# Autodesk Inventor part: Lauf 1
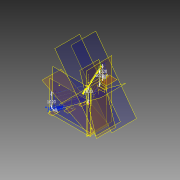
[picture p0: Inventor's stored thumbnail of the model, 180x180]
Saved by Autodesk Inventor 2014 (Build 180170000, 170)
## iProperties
Created: 2013-09
Part Number: Lauf 1
Material: Edelstahl
Document SubType Name: Modeling
Designer: Stefan Tammegger
Mass: 722.325 g
Surface Area: 345.591 cm^2
Volume: 89.3967 cm^3
Density: 8.08 g/cm^3
Appearance: Halbpoliert
Author: Stefan Tammegger
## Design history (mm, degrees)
workplane "Arbeitsebene1"
sketch "Skizze1"
  geometry: L1 (-327.111, -31.202)-(2120.889, -31.202) reference; L2 (0, 0)-(0, -500) reference; L3 (-280, 0)-(-280, -500) reference; L4 (-250, -51.202)-(-140, -51.202); L5 (-140, -51.202)-(-140, -131.202); L6 (-140, -131.202)-(-250, -131.202); L7 (-250, -131.202)-(-250, -51.202); C1 r 5.5 at (-235, -91.202); C2 r 5.5 at (-155, -91.202)
  constraints: 8 end point, 2 centre point, 2 parallel, 1 horizontal, 1 perpendicular
  dimensions: "d0" = 80 distance of L4.end L5.end; "d2" = 20 distance between parallel lines of L1 L4; "d3" = 30 distance between parallel lines of L3 L7; "d4" = 110 distance of L5.end L6.end; "d5" = 11 diameter of C1; "d6" = 15 distance from line of L7 C1.centre; "d7" = 40 distance from line of L4 C1.centre; "d8" = 11 diameter of C2; "d9" = 15 distance from line of L5 C2.centre; "d10" = 40 distance from line of L4 C2.centre
extrude "Extrusion1" new body sketch "Skizze1" distance "d11" = 6; taper "d12" = 0 deg
fillet "Rundung1" dims "d13" = 3
workplane "Arbeitsebene2"
sketch "Skizze2"
  geometry: L1 (-2417.111, -31.202)-(30.889, -31.202) reference; L2 (30.889, -31.202)-(-4.785, 1331.151) reference; L3 (268.82, -224.082)-(-1.666, 65.979) reference; L4 (0, 0)-(0, -500) reference; L5 (20.889, -51.202)-(100.889, -51.202); L6 (100.889, -51.202)-(100.889, -131.202); L7 (100.889, -131.202)-(20.889, -131.202); L8 (20.889, -131.202)-(20.889, -51.202); L9 (-2233, -51.202)-(-2337, -51.202) reference; C1 r 5.5 at (35.889, -91.202); 1 further point
  constraints: 8 end point, 2 parallel, 1 centre point, 1 horizontal, 1 perpendicular
  dimensions: "d14" = 80 distance of L5.end L6.end; "d15" = 80 distance of L5.start L5.end; "d16" = 0 distance between parallel lines of L5 L9; "d17" = 70 horizontal distance of L5.end L1.end; "d21" = 11 diameter of C1; "d22" = 15 distance from line of L8 C1.centre
extrude "Extrusion3" new body sketch "Skizze2" distance "d23" = 6; taper "d24" = 0 deg
fillet "Rundung3" dims "d25" = 3
workplane "Arbeitsebene3"
workplane "Arbeitsebene4"
sketch "Skizze4"
  geometry: L1 (-280, 0)-(-280, -500) reference; L2 (0, 0)-(0, -500) reference; L3 (-195, -51.202)-(-85, -51.202); L4 (-85, -51.202)-(-85, -131.202); L5 (-85, -131.202)-(-195, -131.202); L6 (-195, -131.202)-(-195, -51.202); L7 (-1263, -51.202)-(-1367, -51.202) reference; C1 r 5.5 at (-180, -91.202); C2 r 5.5 at (-100, -91.202); 1 further point
  constraints: 8 end point, 2 centre point, 2 parallel, 1 horizontal, 1 perpendicular
  dimensions: "d39" = 110 distance of L4.end L5.end; "d40" = 80 distance of L3.end L4.end; "d41" = 0 distance between parallel lines of L7 L3; "d42" = 85 distance between parallel lines of L1 L6; "d43" = 11 diameter of C1; "d44" = 11 diameter of C2; "d45" = 15 distance from line of L6 C1.centre; "d46" = 15 distance from line of L4 C2.centre; "d47" = 40 distance from line of L5 C1.centre; "d48" = 40 distance from line of L5 C2.centre
extrude "Extrusion5" new body sketch "Skizze4" distance "d49" = 6; taper "d50" = 0 deg
fillet "Rundung5" dims "d51" = 3
sketch "Skizze5"
  geometry: L1 (-247, -131.202)-(-143, -131.202) reference; L2 (-250, -54.202)-(-250, -128.202) reference; L3 (-210, -66.202)-(-180, -66.202); L4 (-180, -66.202)-(-180, -116.202); L5 (-180, -116.202)-(-210, -116.202); L6 (-210, -116.202)-(-210, -66.202); L7 (-182, -68.202)-(-208, -68.202); L8 (-208, -68.202)-(-208, -114.202); L9 (-208, -114.202)-(-182, -114.202); L10 (-182, -114.202)-(-182, -68.202); 2 further points
  constraints: 16 end point, 4 parallel, 2 perpendicular, 1 horizontal, 1 midpoint, 3 other
  dimensions: "d87" = 30 distance of L3.start L3.end; "d88" = 50 distance of L5.end L3.start; "d89" = 40 distance between parallel lines of L2 L6; "d90" = 15 distance between parallel lines of L1 L5; "d91" = 2 distance between parallel lines of L4 L10
workplane "Arbeitsebene5"
workplane "Arbeitsebene9"
  workplane "Arbeitsebene8"
sketch "Skizze11"
  geometry: L1 (70, -6)-(70, -186) reference; L2 (-210, -6)-(70, -6) reference; L3 (-2300, 1607)-(-2120, 1607) reference; L4 (-2120, 1607)-(-2120, 1426) reference; L5 (70, -6)-(70, 1014); L6 (-2120, 2627)-(-2399.312, 2627); L7 (-2397.889, 1613)-(-2323.889, 1613) reference; L8 (-2400.889, 1613)-(-2400.889, 1607) reference; L9 (-2400.889, 1613)-(-2397.889, 1613) reference; L10 (-2400.889, 1613)-(-2399.312, 2627); L11 (70, -6)-(-2120, 1607); L12 (70, 1014)-(-2120, 2627); L13 (40, -6)-(40, 0) reference; L14 (0, 0)-(0, 1065.557); 4 further points
  constraints: 12 end point, 4 coincident, 3 parallel, 1 perpendicular, 1 point on line
  dimensions: "d92" = 1020 distance of L1.start L5.end; "d93" = 1020 distance between parallel lines of L6 L3; "d94" = 40 distance between parallel lines of L13 L14
  node "Referenz17"
  node "Referenz18"
  node "Referenz19"
  node "Referenz20"
sketch "3D-Skizze2"
feature "Sweeping1" sketch "3D-Skizze2" dims "d95" = 0
workplane "Arbeitsebene10"
sketch "Skizze12"
  geometry: L1 (-70.631, 56.55)-(24.286, 56.55); L2 (24.286, 56.55)-(24.286, -32.474); L3 (24.286, -32.474)-(-70.631, -32.474); L4 (-70.631, -32.474)-(-70.631, 56.55); 1 further point
  constraints: 8 end point, 2 parallel, 1 horizontal, 1 perpendicular
feature "Umgrenzungsfläche1" sketch "Skizze12"
feature "Trennen1"
  node "Volumenkörper10"
workplane "Arbeitsebene11"
sketch "Skizze13"
  geometry: L1 (-86.059, 58.485)-(38.538, 58.485); L2 (38.538, 58.485)-(38.538, -47.075); L3 (38.538, -47.075)-(-86.059, -47.075); L4 (-86.059, -47.075)-(-86.059, 58.485); 1 further point
  constraints: 8 end point, 2 parallel, 1 horizontal, 1 perpendicular
feature "Umgrenzungsfläche2" sketch "Skizze13"
feature "Trennen2"
  node "Volumenkörper11"
workplane "Arbeitsebene12"
sketch "Skizze14"
  geometry: L1 (-76.122, 62.253)-(39.806, 62.253); L2 (39.806, 62.253)-(39.806, -34.033); L3 (39.806, -34.033)-(-76.122, -34.033); L4 (-76.122, -34.033)-(-76.122, 62.253); 1 further point
  constraints: 8 end point, 2 parallel, 1 horizontal, 1 perpendicular
feature "Umgrenzungsfläche3" sketch "Skizze14"
feature "Trennen3"
  node "Volumenkörper13"
sketch "Skizze15"
  geometry: L1 (-88, -51.202)-(-192, -51.202) reference; L2 (-195, -54.202)-(-195, -128.202) reference; L3 (-155, -66.202)-(-125, -66.202); L4 (-125, -66.202)-(-125, -116.202); L5 (-125, -116.202)-(-155, -116.202); L6 (-155, -116.202)-(-155, -66.202); L7 (-127, -68.202)-(-153, -68.202); L8 (-153, -68.202)-(-153, -114.202); L9 (-153, -114.202)-(-127, -114.202); L10 (-127, -114.202)-(-127, -68.202); 1 further point
  constraints: 16 end point, 4 parallel, 2 perpendicular, 1 horizontal, 3 other
  dimensions: "d96" = 30 distance of L3.start L3.end; "d97" = 50 distance of L3.end L4.end; "d98" = 15 distance between parallel lines of L1 L3; "d99" = 40 distance between parallel lines of L2 L6; "d100" = 2 distance between parallel lines of L6 L8
extrude "Extrusion10" new body sketch "Skizze15" stored distance "d101" = 6; taper "d102" = 0 deg
feature "Trennen4"
sketch "Skizze16"
  geometry: L1 (97.889, -51.202)-(23.889, -51.202) reference; L2 (100.889, -128.202)-(100.889, -54.202) reference; L3 (50.889, -66.202)-(100.889, -66.202); L4 (100.889, -66.202)-(100.889, -116.202); L5 (100.889, -116.202)-(50.889, -116.202); L6 (50.889, -116.202)-(50.889, -66.202); L7 (98.889, -68.202)-(52.889, -68.202); L8 (52.889, -68.202)-(52.889, -114.202); L9 (52.889, -114.202)-(98.889, -114.202); L10 (98.889, -114.202)-(98.889, -68.202); 1 further point
  constraints: 16 end point, 4 parallel, 2 perpendicular, 1 horizontal, 3 other
  dimensions: "d103" = 50 distance of L4.end L5.end; "d104" = 50 distance of L5.end L3.start; "d105" = 0 distance between parallel lines of L2 L4; "d106" = 15 distance between parallel lines of L1 L3; "d107" = 2 distance between parallel lines of L3 L7
extrude "Extrusion11" new body sketch "Skizze16" distance "d108" = 1800; taper "d109" = 0 deg
sketch "Skizze18"
  geometry: L1 (97.889, -51.202)-(23.889, -51.202) reference; L2 (20.889, -54.202)-(20.889, -128.202) reference; L3 (23.889, -131.202)-(97.889, -131.202) reference; L4 (100.889, -128.202)-(100.889, -54.202) reference; L5 (50.889, -66.202)-(100.889, -66.202) reference; L6 (100.889, -116.202)-(50.889, -116.202) reference; C1 r 5.5 at (35.889, -91.202) reference; A1 r 3 centre (97.889, -54.202) between (100.889, -54.202) and (97.889, -51.202) reference; A2 r 3 centre (23.889, -54.202) between (23.889, -51.202) and (20.889, -54.202) reference; A3 r 3 centre (23.889, -128.202) between (20.889, -128.202) and (23.889, -131.202) reference; A4 r 3 centre (97.889, -128.202) between (97.889, -131.202) and (100.889, -128.202) reference; 1 further point
sketch "Skizze21"
  geometry: L1 (97.889, -51.202)-(23.889, -51.202) reference; L2 (20.889, -54.202)-(20.889, -128.202) reference; L3 (23.889, -131.202)-(97.889, -131.202) reference; L4 (100.889, -128.202)-(100.889, -54.202) reference; L5 (50.889, -66.202)-(100.889, -66.202) reference; C1 r 5.5 at (35.889, -91.202) reference; A1 r 3 centre (97.889, -54.202) between (100.889, -54.202) and (97.889, -51.202) reference; A2 r 3 centre (23.889, -54.202) between (23.889, -51.202) and (20.889, -54.202) reference; A3 r 3 centre (23.889, -128.202) between (20.889, -128.202) and (23.889, -131.202) reference; A4 r 3 centre (97.889, -128.202) between (97.889, -131.202) and (100.889, -128.202) reference; 2 further points
  constraints: 1 midpoint
workplane "Arbeitsebene15"
  workplane "Arbeitsebene14"
workplane "Arbeitsebene16"
sketch "Skizze23"
  geometry: L1 (0, -0.654)-(-1800, -0.654) reference; L2 (-1014, 6.698)-(-1014, -43.284) reference; L3 (-1014, -43.284)-(-1014, -50.596) reference; L4 (-1014, -0.613)-(-1014, -50.596) reference; L5 (-1014, 6.698)-(-1014, -0.613) reference; L6 (-707, 866.166)-(-884, 866.166) reference; L7 (-884, 866.166)-(-884, 1536.745) reference; L8 (-173, 362.166)-(-349, 362.166) reference; L9 (-349, 362.166)-(-349, 530.166) reference; L10 (-884, 866.166)-(-349, 362.166); L11 (-1904, 1150.048)-(-1904, 866.166); L12 (-1904, 866.166)-(-1014, 27.736); L13 (-1014, -0.613)-(-1014, 27.736); L14 (-890, 1190.048)-(-1829.855, 1190.048); L15 (-884, 1150.048)-(-1904, 1150.048); 6 further points
  constraints: 12 end point, 4 coincident, 4 parallel, 2 point on line, 1 perpendicular
  dimensions: "d136" = 1020 distance between parallel lines of L11 L7; "d137" = 40 distance between parallel lines of L15 L14
  node "Projizierte Kontur1"
  node "Referenz29"
  node "Referenz30"
  node "Referenz31"
  node "Referenz32"
workplane "Arbeitsebene18"
sketch "Skizze25"
  geometry: L1 (-1014, 50)-(-1014, 0) reference; L2 (-984, 50)-(-984, 0) reference; L3 (-1014, 0)-(-984, 0); L4 (-984, 0)-(-984, 50); L5 (-984, 50)-(-1014, 50); L6 (-1014, 50)-(-1014, 0); L7 (-1012, 2)-(-986, 2); L8 (-986, 2)-(-986, 48); L9 (-986, 48)-(-1012, 48); L10 (-1012, 48)-(-1012, 2); 1 further point
  constraints: 16 end point, 4 parallel, 2 perpendicular, 1 horizontal, 3 other
  dimensions: "d149" = 2 distance between parallel lines of L1 L10
extrude "Extrusion13" new body sketch "Skizze25" stored distance "d150" = 10; taper "d151" = 0 deg
feature "Kombinieren2"
  node "Volumenkörper22"
workplane "Arbeitsebene26"
workaxis "Arbeitsachse1"
workplane "Arbeitsebene29"
  workaxis "Arbeitsachse2"
sketch "Skizze31"
  geometry: L1 (346.387, -821.279)-(-1908.319, -821.279) reference; L2 (-70.631, -50.469)-(24.286, -50.469) reference; L3 (-50, -875.752)-(-50, -30) reference; L4 (-50, -30)-(0, -30) reference; C1 r 6 at (-25, -213); C2 r 6 at (-25, -762); C3 r 6 at (-25, -396); C4 r 6 at (-25, -579); 1 further point
  constraints: 4 centre point
  dimensions: "d168" = 12 diameter of C1; "d169" = 25 distance from line of L3 C1.centre; "d170" = 12 diameter of C2; "d173" = 12 diameter of C3; "d174" = 12 diameter of C4; "d175" = 183 distance of C3.centre C1.centre; "d176" = 183 distance of C4.centre C3.centre; "d177" = 183 distance of C2.centre C4.centre; "d192" = 183 distance from line of L4 C1.centre
extrude "Extrusion17" new body sketch "Skizze31" stored distance "d178" = 10; taper "d179" = 0 deg
workplane "Arbeitsebene30"
sketch "Skizze32"
  geometry: L1 (-50, -30)-(0, -30) reference; L2 (-50, 0)-(-50, -30) reference; C1 r 6 at (-25, -213); C2 r 6 at (-25, -396); C3 r 6 at (-25, -579); C4 r 6 at (-25, -762); 1 further point
  constraints: 4 centre point
  dimensions: "d181" = 12 diameter of C1; "d182" = 25 distance from line of L2 C1.centre; "d183" = 183 distance from line of C1.centre L1; "d184" = 12 diameter of C2; "d185" = 12 diameter of C3; "d186" = 12 diameter of C4; "d187" = 183 distance of C2.centre C1.centre; "d188" = 183 distance of C3.centre C2.centre; "d189" = 183 distance of C4.centre C3.centre
extrude "Extrusion18" new body sketch "Skizze32" stored distance "d190" = 10; taper "d191" = 0 deg
workaxis "Arbeitsachse3"
workplane "Arbeitsebene35"
feature "Trennen11"
sketch "Skizze34"
  geometry: L1 (97.889, -51.202)-(23.889, -51.202) reference; L2 (20.889, -54.202)-(20.889, -128.202) reference; L3 (23.889, -131.202)-(97.889, -131.202) reference; L4 (100.889, -128.202)-(100.889, -54.202) reference; L5 (50.889, -116.202)-(50.889, -66.202) reference; L6 (50.889, -66.202)-(100.889, -66.202) reference; C1 r 5.5 at (35.889, -91.202) reference; A1 r 3 centre (97.889, -54.202) between (100.889, -54.202) and (97.889, -51.202) reference; A2 r 3 centre (23.889, -54.202) between (23.889, -51.202) and (20.889, -54.202) reference; A3 r 3 centre (23.889, -128.202) between (20.889, -128.202) and (23.889, -131.202) reference; A4 r 3 centre (97.889, -128.202) between (97.889, -131.202) and (100.889, -128.202) reference; 2 further points
  constraints: 1 midpoint
workplane "Arbeitsebene37"
  workplane "Arbeitsebene36"
sketch "Skizze35"
  geometry: L1 (-707, 698.166)-(-707, 866.166) reference; L2 (-529, 698.166)-(-707, 698.166) reference; L3 (-173, -162.876)-(-173, 134.166) reference; L4 (-173, -162.876)-(-173, 134.166) reference; L5 (-173, 68.166)-(-173, -162.876) reference; L6 (0, -0.654)-(-984, -0.654) reference; L7 (-707, 698.166)-(-173, -0.654); 2 further points
  constraints: 2 end point, 2 point on line
  node "Referenz33"
  node "Referenz34"
  node "Referenz35"
  node "Referenz36"
  node "Referenz37"
workplane "Arbeitsebene38"
sketch "Skizze36"
  geometry: L1 (0, 74.068)-(534, 74.068) reference; 3 further points
  constraints: 1 coincident
  dimensions: "d209" = 1020 distance of point (-1020, 74.068) point (0, 74.068)
workplane "Arbeitsebene39"
sketch "Skizze37"
  geometry: L1 (25, 810.464)-(-25, 810.464); L2 (-25, 810.464)-(-25, 780.464); L3 (-25, 780.464)-(25, 780.464); L4 (25, 780.464)-(25, 810.464); L5 (23, 782.464)-(-23, 782.464); L6 (-23, 782.464)-(-23, 808.464); L7 (-23, 808.464)-(23, 808.464); L8 (23, 808.464)-(23, 782.464); 2 further points
  constraints: 16 end point, 4 parallel, 2 perpendicular, 1 horizontal, 3 other
  dimensions: "d210" = 30 distance of L3.end L1.start; "d211" = 50 distance of L1.start L1.end; "d212" = 25 distance from line of point (0, 810.464) L2; "d213" = 0 distance from line of point (0, 810.464) L1; "d214" = 2 distance between parallel lines of L3 L5
extrude "Extrusion20" new body sketch "Skizze37" stored distance "d215" = 1700; taper "d216" = 0 deg
workplane "Arbeitsebene40"
sketch "Skizze38"
  geometry: L1 (188.25, 50)-(138.25, 50) reference; L2 (188.25, 0)-(188.25, 50) reference; L3 (138.25, 0)-(188.25, 0) reference; L4 (188.25, 50)-(138.25, 50); L5 (138.25, 50)-(138.25, 0); L6 (138.25, 0)-(188.25, 0); L7 (188.25, 0)-(188.25, 50); L8 (140.25, 48)-(186.25, 48); L9 (186.25, 48)-(186.25, 2); L10 (186.25, 2)-(140.25, 2); L11 (140.25, 2)-(140.25, 48); 1 further point
  constraints: 16 end point, 4 parallel, 2 perpendicular, 1 horizontal, 3 other
  dimensions: "d218" = 2 distance between parallel lines of L8 L1
extrude "Extrusion21" new body sketch "Skizze38" distance "d219" = 300; taper "d220" = 0 deg
workplane "Arbeitsebene41"
feature "Trennen12"
sketch "Skizze39"
  geometry: L1 (0, 0)-(0, 1700) reference; L2 (30, 0)-(0, 0) reference; L3 (30, 1700)-(30, 0) reference; L4 (0, 1700)-(30, 1700) reference; L5 (166.066, 462.922)-(-72.306, 645.073) reference; L6 (135.718, 423.207)-(-102.654, 605.358) reference; 3 further points
  constraints: 4 point on line
sketch "Skizze40"
  geometry: L1 (0, 1700)-(0, 0) reference; L2 (30, 0)-(0, 0) reference; L3 (30, 1700)-(30, 0) reference; L4 (0, 1700)-(30, 1700) reference; L5 (-106.512, 424.247)-(131.859, 606.398) reference; 2 further points
  constraints: 2 point on line
workplane "Arbeitsebene42"
feature "Trennen13"
feature "Trennen14"
feature "Kombinieren4"
  node "Volumenkörper18"
workplane "Arbeitsebene43"
sketch "Skizze41"
  geometry: L1 (48.651, 16.578)-(73.016, -913.896) reference; L2 (123.034, -913.896)-(98.634, 17.886) reference; L3 (4.398, -167.942)-(504.226, -154.854) reference; L4 (0, 0)-(499.829, 13.088) reference; L5 (34.528, -17.102)-(37.407, -127.064); L6 (37.407, -127.064)-(117.38, -124.97); L7 (117.38, -124.97)-(114.5, -15.008); L8 (114.5, -15.008)-(34.528, -17.102); C1 r 5.5 at (74.907, -31.05); C2 r 5.5 at (77.001, -111.022); 1 further point
  constraints: 8 end point, 2 centre point, 2 perpendicular, 1 parallel
  dimensions: "d222" = 110 distance of L5.start L5.end; "d223" = 80 distance of L5.end L6.end; "d224" = 110 distance of L6.end L7.end; "d226" = 15 distance between parallel lines of L7 L2; "d227" = 40 distance between parallel lines of L3 L6; "d228" = 11 diameter of C1; "d229" = 11 diameter of C2; "d230" = 15 distance from line of L8 C1.centre; "d231" = 15 distance from line of L6 C2.centre; "d232" = 40 distance from line of L5 C2.centre; "d233" = 40 distance from line of L5 C1.centre
extrude "Extrusion22" new body sketch "Skizze41" distance "d234" = 6; taper "d235" = 0 deg
fillet "Rundung6" dims "d236" = 4
sketch "Skizze42"
  geometry: L1 (110.502, -15.113)-(38.527, -16.997) reference; L2 (48.651, 16.578)-(73.016, -913.896) reference; L3 (123.034, -913.896)-(98.634, 17.886) reference; L4 (50.57, -56.696)-(100.553, -55.387); L5 (100.553, -55.387)-(101.338, -85.377); L6 (101.338, -85.377)-(51.355, -86.685); L7 (51.355, -86.685)-(50.57, -56.696); L8 (98.606, -57.438)-(52.622, -58.643); L9 (52.622, -58.643)-(53.302, -84.634); L10 (53.302, -84.634)-(99.286, -83.43); L11 (99.286, -83.43)-(98.606, -57.438); 1 further point
  constraints: 16 end point, 4 perpendicular, 3 other
  dimensions: "d237" = 50 distance of L4.start L4.end; "d238" = 30 distance of L4.end L5.end; "d239" = 50 distance of L5.end L6.end; "d240" = 0 distance between parallel lines of L3 L5; "d241" = 40 distance between parallel lines of L1 L4; "d242" = 2 distance between parallel lines of L4 L8
extrude "Extrusion23" new body sketch "Skizze42" distance "d243" = 1200; taper "d244" = 0 deg
sketch "Skizze43"
  geometry: L1 (0, -1173.085)-(30, -1133.104) reference; L2 (30, 0)-(30, -1133.104) reference; L3 (0, 0)-(30, 0) reference; L4 (0, -1173.085)-(0, 0) reference; L5 (872.485, -758.954)-(-81.002, -30.351) reference; L6 (854.27, -782.791)-(-99.217, -54.189) reference; 3 further points
  constraints: 4 point on line
sketch "Skizze44"
  geometry: L1 (0, -1131.457)-(30, -1171.438) reference; L2 (30, 0)-(30, -1171.438) reference; L3 (0, 0)-(30, 0) reference; L4 (0, 0)-(0, -1131.457) reference; L5 (-842.485, -758.954)-(111.002, -30.351) reference; 2 further points
  constraints: 2 point on line
workplane "Arbeitsebene44"
feature "Trennen15"
feature "Trennen16"
workplane "Arbeitsebene45"
sketch "Skizze45"
  geometry: L1 (-49.991, 0)-(-0.009, 0) reference; L2 (-50, 30)-(-50, 0) reference; L3 (-50, 0)-(0, 0) reference; L4 (0, 0)-(-50, 0) reference; C1 r 6 at (-25, -185); C2 r 6 at (-25, -370); C3 r 6 at (-25, -555); C4 r 6 at (-25, -740); 4 further points
  constraints: 4 centre point
  dimensions: "d245" = 12 diameter of C1; "d246" = 12 diameter of C2; "d247" = 12 diameter of C3; "d248" = 12 diameter of C4; "d249" = 185 distance from line of C1.centre L1; "d250" = 185 distance of C2.centre C1.centre; "d251" = 185 distance of C3.centre C2.centre; "d252" = 185 distance of C4.centre C3.centre; "d253" = 25 distance from line of C1.centre L2; "d254" = 25 distance from line of C2.centre L2; "d255" = 25 distance from line of C3.centre L2; "d256" = 25 distance from line of C4.centre L2
extrude "Extrusion24" new body sketch "Skizze45" stored distance "d257" = 1200; taper "d258" = 0 deg
node "Volumenkörper1"
node "Referenz1"
node "Referenz2"
node "Referenz3"
node "Referenz4"
node "Referenz5"
node "Referenz6"
node "Referenz7"
node "Volumenkörper3"
node "Referenz11"
node "Referenz12"
node "Volumenkörper5"
node "Fläche1"
node "Fläche2"
node "Fläche3"
node "Volumenkörper17"
node "Volumenkörper28"
node "Volumenkörper29"
node "Volumenkörper31"
node "Volumenkörper32"
node "Referenz38"
node "Referenz39"
node "Volumenkörper33"
node "Volumenkörper34"
node "Volumenkörper35"
node "Projizierte Kontur4"
node "Volumenkörper12"
node "Volumenkörper14"
node "Volumenkörper15"
node "Volumenkörper16"
other parameters: "d148" = 138.25, "d165" = 90 deg, "d167" = 90 deg, "d180" = -1767, "d208" = 0, "d217" = 0, "d221" = 0
